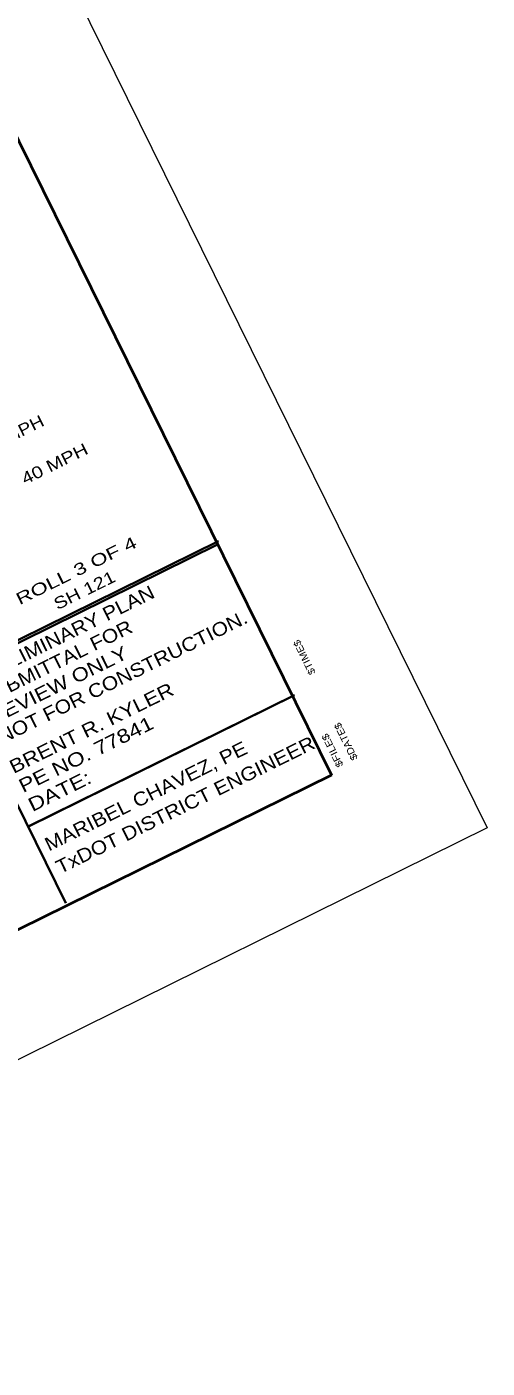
# Model space of a CAD drawing. Extents: x 2356606 to 2371222, y 6973096 to 6982644.
# Drawn here: x 2370608 to 2371004, y 6978951 to 6980104 of the extents above; entities that cross this region are included whole.
import ezdxf
from ezdxf.enums import TextEntityAlignment as Align

# ---------------------------------------------------------------- set-up
doc = ezdxf.new("R2010")
doc.units = 0
doc.header["$LTSCALE"] = 2
for name, color, linetype, lineweight in [('44', 7, 'Continuous', 13), ('62', 7, 'Continuous', 13), ('63', 7, 'Continuous', 13)]:
    doc.layers.add(name, color=color, linetype=linetype, lineweight=lineweight)
doc.layers.add('60', color=7, linetype='Continuous')

msp = doc.modelspace()

# ---------------------------------------------------------------- linework, layer by layer
at = {"layer": '44'}
msp.add_line((2369410.317, 6982643.959), (2371003.634, 6979415.568), dxfattribs=at)
at = {"layer": '44', "lineweight": 40}
msp.add_line((2369364.897, 6982510.022), (2370869.698, 6979460.986), dxfattribs=at)
at = {"layer": '62', "lineweight": 35}
for p, q in [((2370772.563, 6979661.979), (2370188.769, 6979373.856)), ((2370641.531, 6979350.877), (2370543.728, 6979549.041)), ((2370837.859, 6979529.675), (2370609.025, 6979416.738))]:
    msp.add_line(p, q, dxfattribs=at)
at = {"layer": '62', "lineweight": 40}
msp.add_line((2370869.698, 6979460.986), (2358244.847, 6973230.201), dxfattribs=at)
at = {"layer": '62'}
msp.add_line((2371003.634, 6979415.568), (2358199.427, 6973096.266), dxfattribs=at)
at = {"layer": '63', "lineweight": 35}
for p, q in [((2370771.897, 6979659.152), (2370188.104, 6979371.029)), ((2370837.859, 6979529.675), (2370608.639, 6979416.548))]:
    msp.add_line(p, q, dxfattribs=at)
at = {"layer": '63', "lineweight": 40}
msp.add_line((2370869.698, 6979460.986), (2358244.847, 6973230.201), dxfattribs=at)
at = {"layer": '63'}
msp.add_line((2371003.634, 6979415.568), (2358199.427, 6973096.266), dxfattribs=at)

# ---------------------------------------------------------------- texts
at = {"layer": '60'}
for s, width, p in [('$TIME$', 1.15, (2370856.283, 6979548.893)), ('$DATE$', 1.15, (2370892.558, 6979475.391)), ('$FILE$', 1.2, (2370880.132, 6979469.409))]:
    msp.add_text(s, height=6, rotation=116.268, dxfattribs=dict(at, width=width)).set_placement(p)
at = {"layer": '62'}
for s, width, p in [('DIRECT CONNECTOR & RAMP DESIGN SPEED = 50 MPH', 1.2, (2370425.126, 6979663.505)), ('FRONTAGE ROAD DESIGN SPEED VARIABLE 35 TO 40 MPH', 1.25, (2370442.894, 6979629.485)), ('ROLL 3 OF 4', 1.4, (2370652.643, 6979632.005)), ('SH 121 ', 1.25, (2370661.841, 6979616.187))]:
    msp.add_text(s, height=10.2, rotation=26.268, dxfattribs=dict(at, width=width)).set_placement(p, align=Align.CENTER)
for s, width, p in [('PRELIMINARY PLAN', 1.15, (2370562.428, 6979536.614)), ('SUBMITTAL FOR', 1.15, (2370570.502, 6979520.256)), ('NOT FOR CONSTRUCTION.', 1.15, (2370586.649, 6979487.539)), ('REVIEW ONLY', 1.2, (2370578.575, 6979503.898)), ('BRENT R. KYLER', 1.2, (2370596.614, 6979461.832)), ('PE NO. 77841', 1.25, (2370604.685, 6979445.478)), ('MARIBEL CHAVEZ, PE', 1.15, (2370626.91, 6979395.196)), ('TxDOT DISTRICT ENGINEER', 1.15, (2370636.532, 6979375.702)), ('DATE: ', 1.25, (2370612.756, 6979429.127))]:
    msp.add_text(s, height=11.74, rotation=26.268, dxfattribs=dict(at, width=width)).set_placement(p)
at = {"layer": '63', "width": 1.2}
msp.add_text('DIRECT CONNECTOR & RAMP DESIGN SPEED = 50 MPH', height=10.2, rotation=26.268, dxfattribs=at).set_placement((2370425.126, 6979663.505), align=Align.CENTER)

doc.saveas('drawing.dxf')
